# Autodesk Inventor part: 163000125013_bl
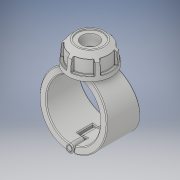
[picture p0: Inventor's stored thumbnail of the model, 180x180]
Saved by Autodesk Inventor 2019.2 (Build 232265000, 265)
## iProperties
Created: 2022-02
Part Number: 163000125013_bl
Material: Generic
Description: Plassadle Threaded 125x1 1/4''
Document SubType Name: Modeling
Designer: comp2
Density: 1 g/cm^3
Appearance: Default
Author: comp2
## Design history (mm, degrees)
derived "16300.ipt"
feature "Solid1::16300.ipt" dims "ScaleForDerivedMember" = 10
feature "Solid2::16300.ipt" dims "ScaleForDerivedMember" = 10
feature "Solid3::16300.ipt" dims "ScaleForDerivedMember" = 10
feature "Solid4::16300.ipt" dims "ScaleForDerivedMember" = 10
tag "TaggingFeature1"
body "Solid1"
body "Solid2"
body "Solid3"
body "Solid4"
other parameters: "d0" = 125 [user parameter], "d2" = 157 [user parameter], "d3" = 62.5 [user parameter], "d7" = 149.15 [user parameter], "d8" = 85 deg [user parameter], "d9" = 45 deg [user parameter], "d10" = 102 [user parameter], "d11" = 49 [user parameter], "d12" = 35.5495 [user parameter], "d13" = 42.84 [user parameter], "d14" = 58.428 [user parameter], "d42" = 3.2 [user parameter], "d49" = 3.14 [user parameter], "d51" = 0 [user parameter], "d52" = 22.4 [user parameter], "d53" = 86.35 [user parameter], "d54" = 35 [user parameter], "d55" = 0 [user parameter], "d59" = 0 [user parameter], "d61" = 0 [user parameter], "d62" = 35 [user parameter], "d63" = 0 [user parameter], "d65" = 0 [user parameter], "d67" = 0 [user parameter], "d69" = 0 [user parameter], "d70" = 1 [user parameter], "d71" = 96 [user parameter], "d72" = 0 [user parameter], "d73" = 2 [user parameter], "d78" = 86.7 [user parameter], "d79" = 5.1 [user parameter], "d80" = 60 deg [user parameter], "d81" = 5.1 [user parameter], "d84" = 0 [user parameter], "d85" = 1 [user parameter], "d87" = 360 deg [user parameter], "d122" = 58 [user parameter], "d124" = 42.80128 [user parameter], "d125" = 2.53925 [user parameter], "d127" = 207 [user parameter], "d129" = 38.952 [user parameter], "d130" = 33.1092 [user parameter], "d131" = 37.7 [user parameter], "d132" = 45 deg [user parameter], "d133" = 26.39 [user parameter], "d134" = 19.476 [user parameter], "d136" = 0 [user parameter], "d138" = 0 [user parameter], "d" = 125 [user parameter], "d1" = 25 [user parameter], "B" = 157 [user parameter], "E_" = 54 [user parameter], "E1" = 102 [user parameter], "H1" = 207 [user parameter], "H2" = 58 [user parameter], "H3" = 78 [user parameter], "H_costum" = 49 [user parameter], "Rp" = 38.952 [user parameter], "d128" = 50.785 [user parameter]
